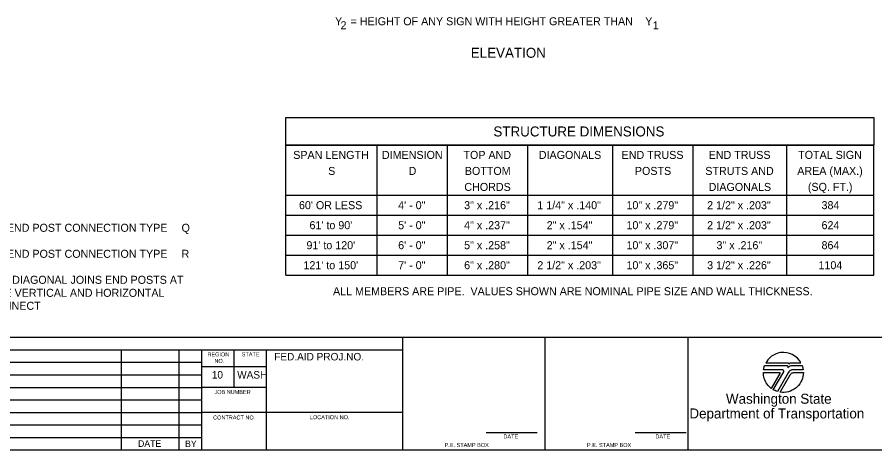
# Model space of a CAD drawing. Extents: x 99862 to 104211, y 98939 to 111076.
# Drawn here: x 100720 to 102434, y 100000 to 100865 of the extents above; entities that cross this region are included whole.
import ezdxf

# ---------------------------------------------------------------- set-up
doc = ezdxf.new("R2010")
doc.units = 0
for name, color, linetype in [('Level 15', 7, 'Continuous'), ('Level 20', 7, 'Continuous'), ('Level 40', 7, 'Continuous'), ('Level 60', 7, 'Continuous'), ('Level 7', 7, 'Continuous')]:
    doc.layers.add(name, color=color, linetype=linetype)

msp = doc.modelspace()

# ---------------------------------------------------------------- linework, layer by layer
at = {"layer": 'Level 20'}
for p, q in [((101773.6, 100365.8), (101773.6, 100365.8)), ((101788.6, 100365.8), (101788.6, 100365.8))]:
    msp.add_line(p, q, dxfattribs=at)
at = {"layer": 'Level 40'}
for p, q in [((101256.6, 100349.2), (101256.6, 100609.4)), ((101256.6, 100609.4), (102431.7, 100609.4)), ((101439, 100349.2), (101439, 100609.4)), ((101579.9, 100349.2), (101579.9, 100609.4)), ((101739.9, 100349.2), (101739.9, 100609.4)), ((101909.9, 100349.2), (101909.9, 100609.4)), ((102070.8, 100349.2), (102070.8, 100609.4)), ((102257.7, 100349.2), (102257.7, 100609.4)), ((102431.7, 100349.2), (102431.7, 100609.4)), ((101256.6, 100509.2), (102431.7, 100509.2)), ((101256.6, 100469.2), (102431.7, 100469.2)), ((101256.6, 100429.2), (102431.7, 100429.2)), ((101256.6, 100389.2), (102431.7, 100389.2)), ((101256.6, 100349.2), (102431.7, 100349.2))]:
    msp.add_line(p, q, dxfattribs=at)
msp.add_lwpolyline([(101256.6, 100664.7), (102431.7, 100664.7), (102431.7, 100609.4), (101256.6, 100609.4)], close=True, dxfattribs=at)
at = {"layer": 'Level 60'}
for p, q in [((100000, 100225), (103150, 100225)), ((101490.1, 100000), (101490.1, 100225)), ((101775.1, 100000), (101775.1, 100225)), ((102060.1, 100225), (102060.1, 100000)), ((100000, 100200), (101490.1, 100200)), ((100927.5, 100200), (100927.5, 100000)), ((101042.5, 100200), (101042.5, 100000)), ((101088.1, 100200), (101088.1, 100000)), ((101153.5, 100125), (101153.5, 100200)), ((101218.1, 100000), (101218.1, 100200)), ((100436.1, 100175), (101088.5, 100175)), ((101218.2, 100166.1), (101088.5, 100166.1)), ((100436.1, 100150), (101088.5, 100150)), ((100000, 100125), (101088.5, 100125)), ((101218.2, 100125), (101088.5, 100125)), ((100000, 100100), (101088.5, 100100)), ((100000, 100075), (101088.5, 100075)), ((101490.1, 100075), (101088.5, 100075)), ((100000, 100050), (101088.5, 100050)), ((100000, 100025), (101088.5, 100025)), ((101656.7, 100034.6), (101759, 100034.6)), ((101954.4, 100034.6), (102056.6, 100034.6)), ((100000, 100000), (103150, 100000))]:
    msp.add_line(p, q, dxfattribs=at)
for points in [[(102215.6, 100173.9), (102259.9, 100173.9), (102260.7, 100173.7), (102261.4, 100173.2), (102261.7, 100172.6), (102261.7, 100172), (102261.5, 100171.2), (102262.3, 100172.2), (102263.5, 100173.1), (102265.2, 100173.8), (102266.4, 100173.9), (102285.9, 100173.9), (102283, 100178.5), (102278.9, 100183.3), (102273.7, 100187.6), (102268.3, 100190.8), (102263.3, 100192.8), (102257.6, 100194.2), (102251.6, 100194.8), (102245.1, 100194.4), (102239.7, 100193.3), (102235.1, 100191.6), (102231.1, 100189.6), (102227.3, 100187.2), (102223.7, 100184.3), (102219.8, 100180.1), (102217.5, 100176.9)], [(102215.6, 100173.9), (102259.9, 100173.9), (102260.7, 100173.7), (102261.4, 100173.2), (102261.7, 100172.6), (102261.7, 100172), (102261.5, 100171.2), (102262.3, 100172.2), (102263.5, 100173.1), (102265.2, 100173.8), (102266.4, 100173.9), (102285.9, 100173.9), (102283, 100178.5), (102278.9, 100183.3), (102273.7, 100187.6), (102268.3, 100190.8), (102263.3, 100192.8), (102257.6, 100194.2), (102251.6, 100194.8), (102245.1, 100194.4), (102239.7, 100193.3), (102235.1, 100191.6), (102231.1, 100189.6), (102227.3, 100187.2), (102223.7, 100184.3), (102219.8, 100180.1), (102217.5, 100176.9)], [(102213.3, 100168.7), (102257.2, 100168.7), (102257.9, 100168.6), (102258.5, 100168.4), (102258.9, 100168.2), (102259.2, 100167.9), (102259.7, 100167.3), (102260, 100166.6), (102260.2, 100165.9), (102260.1, 100165.2), (102260, 100164.7), (102259.7, 100164.2), (102260.2, 100164.9), (102261.1, 100165.9), (102262.1, 100166.8), (102263.4, 100167.6), (102264.6, 100168.1), (102266.5, 100168.6), (102269.2, 100168.7), (102288.3, 100168.7), (102289.1, 100166.2), (102289.6, 100164.5), (102290, 100162.7), (102290.3, 100160.9), (102290.4, 100160.1), (102272, 100160.1), (102269.5, 100160), (102267.7, 100159.7), (102265.2, 100158.7), (102263.2, 100157.2), (102261.8, 100155.7), (102260.6, 100153.7), (102239.1, 100116.6), (102236.5, 100117.5), (102234.2, 100118.5), (102232.2, 100119.5), (102230.7, 100120.3), (102251.5, 100156.1), (102251.9, 100157.4), (102251.6, 100158.6), (102250.7, 100159.6), (102249.9, 100160), (102249.3, 100160.1), (102211.2, 100160.1), (102211.6, 100162.6), (102211.8, 100163.9), (102212.2, 100165.3), (102212.7, 100167)], [(102210.8, 100154.8), (102242.3, 100154.8), (102242.7, 100154.8), (102243.2, 100154.6), (102243.5, 100154.4), (102243.7, 100154.1), (102243.9, 100153.7), (102243.9, 100153.3), (102243.9, 100152.9), (102243.7, 100152.4), (102226.6, 100123), (102224.5, 100124.7), (102222.6, 100126.5), (102220.7, 100128.5), (102218.3, 100131.5), (102216.6, 100134.1), (102215, 100137), (102213.6, 100140.2), (102212.6, 100143), (102211.8, 100146), (102211.2, 100149), (102210.9, 100152)], [(102244.2, 100115.4), (102264.2, 100150), (102264.8, 100150.9), (102265.4, 100151.6), (102266.3, 100152.5), (102267.2, 100153.2), (102268.3, 100153.8), (102269.5, 100154.3), (102270.8, 100154.6), (102271.5, 100154.7), (102272.4, 100154.7), (102290.8, 100154.7), (102290.5, 100150.3), (102290, 100146.9), (102288.8, 100142.5), (102287.6, 100139.3), (102286, 100135.9), (102283.5, 100131.9), (102280.8, 100128.4), (102278.9, 100126.4), (102276.1, 100123.9), (102272.7, 100121.4), (102268.7, 100119.1), (102265, 100117.5), (102260.9, 100116.2), (102256.9, 100115.3), (102252.4, 100114.9), (102249.2, 100114.9), (102246.3, 100115.1)]]:
    msp.add_lwpolyline(points, close=True, dxfattribs=at)

# ---------------------------------------------------------------- texts
at = {"layer": 'Level 15'}
for s, p in [('= HEIGHT OF ANY SIGN WITH HEIGHT GREATER THAN     .', (101386.1, 100848.9)), ('1', (101989.9, 100840.9))]:
    msp.add_text(s, height=16, dxfattribs=at).set_placement(p)
at = {"layer": 'Level 20'}
for s, p in [('Y', (101355, 100848.9)), ('Y', (101974.8, 100848.9)), ('2', (101365.9, 100840.9))]:
    msp.add_text(s, height=16, rotation=0, dxfattribs=at).set_placement(p)
for s, height, p in [('ELEVATION', 20, (101626.2, 100783.9)), ('STRUCTURE DIMENSIONS', 20, (101671.4, 100626.6)), ('SPAN LENGTH', 16, (101271.4, 100581.7)), ('DIMENSION', 16, (101448.7, 100581.7)), ('TOP AND', 16, (101611.6, 100581.7)), ('DIAGONALS', 16, (101762.1, 100581.7)), ('END TRUSS', 16, (101927.6, 100581.7)), ('END TRUSS', 16, (102101.5, 100581.7)), ('TOTAL SIGN', 16, (102280.4, 100581.8)), ('S', 16, (101341.2, 100549.7)), ('D', 16, (101502, 100549.7)), ('BOTTOM', 16, (101614.3, 100549.7)), ('POSTS', 16, (101954.1, 100549.7)), ('STRUTS AND', 16, (102094.8, 100549.7)), ('AREA (MAX.)', 16, (102278.6, 100549.8)), ('(SQ. FT.)', 16, (102299.8, 100517.8)), ('CHORDS', 16, (101613.4, 100517.7)), ('DIAGONALS', 16, (102101.5, 100517.7)), ("60' OR LESS", 16, (101282.9, 100481.2)), ('4\' - 0"', 16, (101481.1, 100481.2)), ('3" x .216"', 16, (101612.9, 100481.2)), ('1 1/4" x .140"', 16, (101759.2, 100481.2)), ('10" x .279"', 16, (101937.3, 100481.2)), ('2 1/2" x .203"', 16, (102098.5, 100481.2)), ('384', 16, (102327.1, 100481.2)), ('SEE CHORD TO END POST CONNECTION TYPE', 16, (100530.3, 100436)), ("61' to 90'", 16, (101303.9, 100441.2)), ('5\' - 0"', 16, (101481.1, 100441.2)), ('4" x .237"', 16, (101612.9, 100441.2)), ('2" x .154"', 16, (101777.9, 100441.2)), ('10" x .279"', 16, (101937.3, 100441.2)), ('2 1/2" x .203"', 16, (102098.5, 100441.2)), ('624', 16, (102327.1, 100441.2)), ("91' to 120'", 16, (101297.8, 100401.2)), ('6\' - 0"', 16, (101481.1, 100401.2)), ('5" x .258"', 16, (101612.9, 100401.2)), ('2" x .154"', 16, (101777.9, 100401.2)), ('10" x .307"', 16, (101937.3, 100401.2)), ('3" x .216"', 16, (102117.2, 100401.2)), ('864', 16, (102327.1, 100401.2)), ('SEE CHORD TO END POST CONNECTION TYPE', 16, (100530.3, 100384)), ("121' to 150'", 16, (101291.8, 100361.2)), ('7\' - 0"', 16, (101481.1, 100361.2)), ('6" x .280"', 16, (101612.9, 100361.2)), ('2 1/2" x .203"', 16, (101759.2, 100361.2)), ('10" x .365"', 16, (101937.3, 100361.2)), ('3 1/2" x .226"', 16, (102098.5, 100361.2)), ('1104', 16, (102321, 100361.2)), ('TOP END TRUSS DIAGONAL JOINS END POSTS AT', 16, (100530.3, 100332)), ('CHORDS WHERE VERTICAL AND HORIZONTAL', 16, (100530.3, 100306)), ('ALL MEMBERS ARE PIPE.  VALUES SHOWN ARE NOMINAL PIPE SIZE AND WALL THICKNESS.', 16, (101350.9, 100309.2)), ('DIAGONALS CONNECT', 16, (100530.3, 100280))]:
    msp.add_text(s, height=height, dxfattribs=at).set_placement(p)
at = {"layer": 'Level 60'}
for s, height, p in [('REGION', 8, (101100, 100186.9)), ('STATE', 8, (101168.5, 100187)), ('FED.AID PROJ.NO.', 15, (101233.5, 100178.8)), ('NO.', 8, (101113.9, 100173.7)), ('10', 15, (101108.7, 100142.5)), ('WASH', 15, (101159.4, 100142.5)), ('JOB NUMBER', 8, (101114, 100111.7)), ('Washington State', 19.999, (102136.1, 100092.2)), ('Department of Transportation', 19.999, (102063.1, 100062.8)), ('CONTRACT NO.', 8, (101111.4, 100060.7)), ('LOCATION NO.', 8, (101304.6, 100061.3)), ('DATE', 8.03, (101691.4, 100022.8)), ('DATE', 8.03, (101995.1, 100022.8)), ('DATE', 13, (100961.3, 100006)), ('BY', 13, (101055.3, 100005.7)), ('P.E. STAMP BOX', 8, (101573.8, 100005.7)), ('P.E. STAMP BOX', 8, (101858.4, 100005.7))]:
    msp.add_text(s, height=height, dxfattribs=at).set_placement(p)
at = {"layer": 'Level 7'}
for s, p in [('Q', (101048.3, 100436)), ('R', (101048.3, 100384))]:
    msp.add_text(s, height=16, dxfattribs=at).set_placement(p)

doc.saveas('drawing.dxf')
